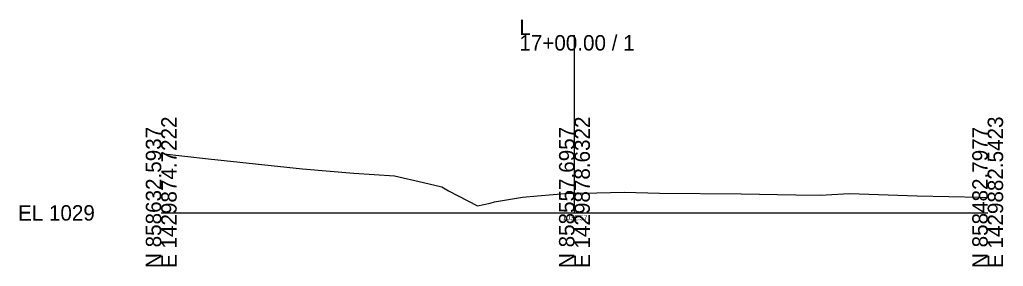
# Model space of a CAD drawing. Extents: x -26 to 153, y -10 to 13058.
# Drawn here: x -25.7 to 152.8, y 10990.3 to 11035 of the extents above; entities that cross this region are included whole.
import ezdxf

# ---------------------------------------------------------------- set-up
doc = ezdxf.new("R2010")
doc.units = 0
for name, color, linetype in [('Default', 7, 'Continuous'), ('Exist Cross Section Cell', 7, 'Continuous'), ('Exist XS Center Line Elevation Label', 7, 'Continuous'), ('Exist XS Ground Line', 7, 'Continuous')]:
    doc.layers.add(name, color=color, linetype=linetype)

msp = doc.modelspace()

# ---------------------------------------------------------------- linework, layer by layer
at = {"layer": 'Exist Cross Section Cell'}
for p, q in [((75, 11000), (75, 11032.25)), ((0, 11000), (75, 11000)), ((75, 11000), (150, 11000))]:
    msp.add_line(p, q, dxfattribs=at)
at = {"layer": 'Exist XS Ground Line'}
msp.add_lwpolyline([(0, 11010.75), (8.59, 11009.8), (25.63, 11008), (34.94, 11007.18), (42.31, 11006.73), (47.6, 11005.52), (50.91, 11004.74), (52.11, 11004.03), (57.42, 11001.25), (59.7, 11001.79), (60.49, 11001.98), (62.69, 11002.37), (65.56, 11002.85), (68.32, 11003.07), (74, 11003.55), (75, 11003.57), (79.06, 11003.66), (84.03, 11003.77), (90.42, 11003.59), (105.24, 11003.43), (115.16, 11003.29), (119.6, 11003.24), (124.93, 11003.49), (137.21, 11003.09), (148.7, 11002.86), (150, 11002.8)], dxfattribs=at)

# ---------------------------------------------------------------- texts
at = {"layer": 'Default'}
msp.add_text('-', height=0.0001, dxfattribs=at).set_placement((0, 11000))
at = {"layer": 'Exist Cross Section Cell'}
for s, p in [('L', (65, 11032.25)), ('17+00.00 / 1', (65, 11029.45)), ('EL 1029', (-26, 10998.6))]:
    msp.add_text(s, height=2.8, dxfattribs=at).set_placement(p)
for s, p in [('E 1429874.7222', (2.8, 10990)), ('E 1429878.6322', (77.8, 10990)), ('E 1429882.5423', (152.8, 10990)), ('N 858632.5937', (0, 10990)), ('N 858557.6957', (75, 10990)), ('N 858482.7977', (150, 10990))]:
    msp.add_text(s, height=2.8, rotation=90, dxfattribs=at).set_placement(p)
at = {"layer": 'Exist XS Center Line Elevation Label'}
msp.add_text('1032.57', height=0.9, dxfattribs=at).set_placement((72.86, 10998.67))
msp.add_text('1032.57', height=0.9, dxfattribs=at).set_placement((72.86, 10998.67))
msp.add_text('1032.57', height=0.9, dxfattribs=at).set_placement((72.86, 10998.67))

doc.saveas('drawing.dxf')
